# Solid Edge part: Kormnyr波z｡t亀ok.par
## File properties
Author: morva
Template: iso metric part.par
Last saved by: morva
Revision: 16
Application: Solid Edge
Density: 2712.000 kg/m^3
Accuracy: 0.990
Username: morva
Material: Aluminum, 6061-T6
Face Style: Aluminum
Fill Style: ANSI38(Aluminum)
Virtual Style: Polished aluminum
Grouping: Metals\Aluminium Alloys
LibraryName: Materials
Coef. of Thermal Exp: 2.3e-05
Thermal Conductivity: 180.0
Specific Heat: 920.0
Modulus of Elasticity: 68947570000.0
Poisson's Ratio: 0.33
Yield Stress: 275790280.0
Ultimate Stress: 310264065.0
Elongation: 0.0
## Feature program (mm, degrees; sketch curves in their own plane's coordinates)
sketch for "unnamed Protrusion 1" plane through (0, 0, 0) normal (0, -1, 0) x-axis (1, 0, 0)
  circle centre (0, 0) radius 11
extrude "unnamed Protrusion 1" add finite 100 along -normal
sketch for "ExtrudedCutout_1" plane through (0, 0, 0) normal (0, -1, 0) x-axis (0, 0, 1)
  line (-9.798, 5) -> (9.798, 5)
  arc centre (0, 0) radius 11 from (9.798, 5) to (9.798, -5) cw
  line (-9.798, -5) -> (9.798, -5)
extrude "ExtrudedCutout_1" cut finite 40 along -normal
sketch for "ExtrudedCutout_2" plane through (-5, 20, 0) normal (1, 0, 0) x-axis (0, -1, 0)
  circle centre (-5, 0) radius 5
extrude "ExtrudedCutout_2" cut finite 42.3461 symmetric
sketch for "ExtrudedCutout_3" plane through (-5, 20, 0) normal (1, 0, 0) x-axis (0, 1, 0)
  line (-18, 9.798) -> (-20.4951, 9.798)
  line (-18, -9.798) -> (-20.4951, -9.798)
extrude "ExtrudedCutout_3" cut finite 44.5266 symmetric
sketch for "ExtrudedProtrusion_2" plane through (0, 100, 0) normal (0, 1, 0) x-axis (1, 0, 0)
  circle centre (0, 0) radius 15
extrude "ExtrudedProtrusion_2" add finite 6 along +normal
sketch for "ExtrudedProtrusion_3" plane through (0, 106, 0) normal (0, 1, 0) x-axis (0, 0, -1)
  circle centre (0, 0) radius 10
extrude "ExtrudedProtrusion_3" add finite 100 along +normal
thread "Thread_3"  ThreadDepth = 35 mm
chamfer "Chamfer_1" setback 2
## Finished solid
Body 1: solid body, 15 faces, 23 edges, 8 vertices.
  Faces by surface: cylinder 8, plane 6, cone 1
  Edges by curve: circle 13, line 6, intersection 4
Bounding box of the edges (mm): 30.000 x 206.000 x 30.000, from (-15, 0, -15) to (15, 206, 15).
Cylindrical faces by radius (mm): R5 x2, R10 x2, R11 x1, R15 x1, R25 x2
Conical faces (half-angle, radius in mm at the cone's reference point): 45 deg R10 x1
Planar faces by outward normal: +x 1, +y 2, -x 1, -y 2
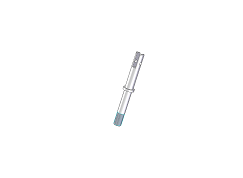
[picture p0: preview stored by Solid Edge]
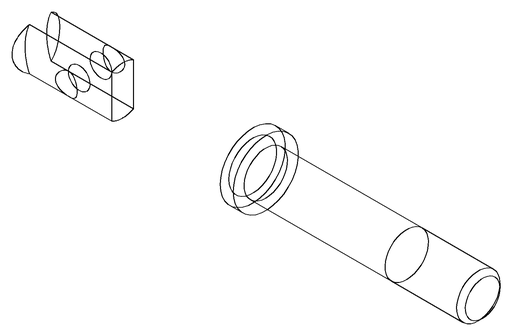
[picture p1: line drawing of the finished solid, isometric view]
